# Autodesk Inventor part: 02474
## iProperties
Author: Administrator
Shininess: 64.0
Angle Display Precision: 2
Document Length Units: 11272
Document Angle Units: 11286
Document Time Units: 11279
Document Mass Units: 11290
Document Length Units Precision: 3
Document Angle Units Precision: 2
Compacted: True
PropertySet Name: _Private Model Information
Created: 2002-04
Part Number: 02474
Material: Stainless Steel, 440C
Document SubType Name: Modeling
Designer: Administrator
Control State: 0
Master: False
Checked Out: False
PropertySet Name: Design Tracking Control
Density: 0.0
Volumn: 0.0
Area: 0.0
PropertySet Name: Model Information
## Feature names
1. Revolution1
